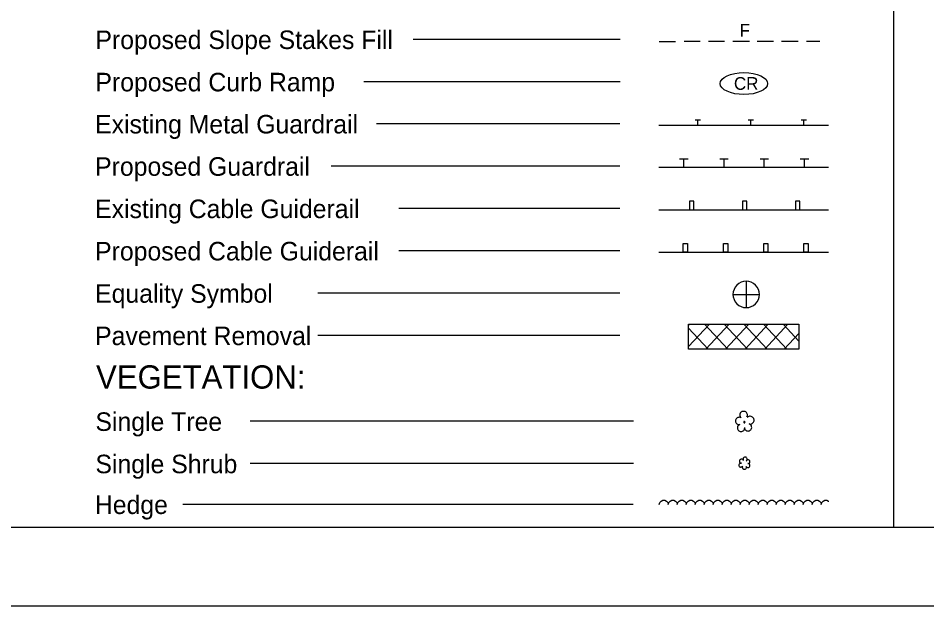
# Model space of a CAD drawing. Extents: x 1855058 to 1858918, y 1540202 to 1542502.
# Drawn here: x 1857551.6 to 1857984.5, y 1541401.8 to 1541681.9 of the extents above; entities that cross this region are included whole.
import ezdxf

# ---------------------------------------------------------------- set-up
doc = ezdxf.new("R2010")
doc.units = 0
for name, color, linetype in [('Default', 7, 'Continuous'), ('Exist Contamination Potential Cell', 7, 'Continuous'), ('Sheet Data Field CELL', 7, 'Continuous'), ('Sheet Symbology CELL', 7, 'Continuous'), ('z - Construction', 7, 'Continuous')]:
    doc.layers.add(name, color=color, linetype=linetype)

msp = doc.modelspace()

# ---------------------------------------------------------------- linework, layer by layer
at = {"layer": 'Default'}
msp.add_lwpolyline([(1857118.6, 1542501.77), (1857118.6, 1541401.77), (1858818.6, 1541401.77), (1858818.6, 1542501.77)], close=True, dxfattribs=at)
at = {"layer": 'Exist Contamination Potential Cell'}
for p, q in [((1857968.6, 1542464.27), (1857968.58, 1541439.27)), ((1857118.6, 1541401.77), (1858818.6, 1541401.77))]:
    msp.add_line(p, q, dxfattribs=at)
at = {"layer": 'Sheet Data Field CELL'}
for p, q in [((1857838.33, 1541671.75), (1857739.72, 1541671.75)), ((1857857.03, 1541670.69), (1857864.69, 1541670.69)), ((1857876.5, 1541670.69), (1857868.88, 1541670.69)), ((1857888.1, 1541670.69), (1857880.43, 1541670.69)), ((1857899.96, 1541670.69), (1857892.09, 1541670.69)), ((1857911.51, 1541670.69), (1857903.69, 1541670.69)), ((1857923.16, 1541670.69), (1857915.24, 1541670.69)), ((1857933.55, 1541670.69), (1857927.1, 1541670.69)), ((1857838.33, 1541651.57), (1857716.32, 1541651.57)), ((1857838.17, 1541631.51), (1857722.31, 1541631.51)), ((1857856.87, 1541630.93), (1857937.58, 1541630.93)), ((1857874.16, 1541633.45), (1857876.68, 1541633.45)), ((1857875.42, 1541630.93), (1857875.42, 1541633.45)), ((1857899.38, 1541633.45), (1857901.9, 1541633.45)), ((1857900.64, 1541630.93), (1857900.64, 1541633.45)), ((1857924.61, 1541633.45), (1857927.13, 1541633.45)), ((1857925.87, 1541630.93), (1857925.87, 1541633.45)), ((1857866.68, 1541614.74), (1857870.72, 1541614.74)), ((1857868.7, 1541610.75), (1857868.7, 1541614.74)), ((1857885.85, 1541614.74), (1857889.89, 1541614.74)), ((1857887.87, 1541610.75), (1857887.87, 1541614.74)), ((1857905.02, 1541614.74), (1857909.06, 1541614.74)), ((1857907.04, 1541610.75), (1857907.04, 1541614.74)), ((1857924.19, 1541614.74), (1857928.22, 1541614.74)), ((1857926.21, 1541610.75), (1857926.21, 1541614.74)), ((1857838.17, 1541611.33), (1857700.72, 1541611.33)), ((1857937.58, 1541610.75), (1857856.87, 1541610.75)), ((1857838.17, 1541591.15), (1857732.94, 1541591.15)), ((1857856.87, 1541590.57), (1857937.58, 1541590.57)), ((1857838.17, 1541570.97), (1857732.94, 1541570.97)), ((1857856.87, 1541570.39), (1857937.58, 1541570.39)), ((1857898.46, 1541556.51), (1857898.46, 1541550.2)), ((1857838.17, 1541550.79), (1857694.27, 1541550.79)), ((1857892.16, 1541550.2), (1857898.46, 1541550.2)), ((1857898.46, 1541550.2), (1857898.46, 1541543.89)), ((1857898.46, 1541550.2), (1857904.77, 1541550.2)), ((1857870.94, 1541535.95), (1857923.51, 1541535.95)), ((1857870.94, 1541524.15), (1857870.94, 1541535.95)), ((1857870.94, 1541535.34), (1857871.5, 1541535.95)), ((1857870.94, 1541525.31), (1857880.88, 1541535.95)), ((1857889.66, 1541524.15), (1857878.56, 1541535.95)), ((1857879.17, 1541524.15), (1857890.26, 1541535.95)), ((1857898.99, 1541524.15), (1857887.94, 1541535.95)), ((1857888.5, 1541524.15), (1857899.65, 1541535.95)), ((1857908.37, 1541524.15), (1857897.28, 1541535.95)), ((1857897.88, 1541524.15), (1857908.98, 1541535.95)), ((1857917.76, 1541524.15), (1857906.61, 1541535.95)), ((1857907.26, 1541524.15), (1857918.31, 1541535.95)), ((1857923.51, 1541527.93), (1857915.99, 1541535.95)), ((1857923.51, 1541535.95), (1857923.51, 1541524.15)), ((1857838.17, 1541530.61), (1857694.27, 1541530.61)), ((1857880.28, 1541524.15), (1857870.94, 1541534.13)), ((1857916.6, 1541524.15), (1857923.51, 1541531.51)), ((1857923.51, 1541524.15), (1857870.94, 1541524.15)), ((1857844.81, 1541489.71), (1857662.07, 1541489.71)), ((1857844.81, 1541469.53), (1857662.07, 1541469.53)), ((1857844.54, 1541450.1), (1857629.95, 1541450.1)), ((1857857.04, 1541450.1), (1857857.35, 1541451.06)), ((1857857.35, 1541451.06), (1857857.95, 1541451.71)), ((1857857.95, 1541451.71), (1857858.76, 1541452.17)), ((1857858.76, 1541452.17), (1857859.72, 1541452.17)), ((1857859.72, 1541452.17), (1857860.52, 1541451.66)), ((1857860.52, 1541451.66), (1857861.08, 1541451.01)), ((1857861.08, 1541451.01), (1857861.28, 1541450.15)), ((1857861.33, 1541450.1), (1857861.63, 1541451.06)), ((1857861.63, 1541451.06), (1857862.24, 1541451.71)), ((1857862.24, 1541451.71), (1857863.05, 1541452.17)), ((1857863.05, 1541452.17), (1857864.01, 1541452.17)), ((1857864.01, 1541452.17), (1857864.81, 1541451.66)), ((1857864.81, 1541451.66), (1857865.37, 1541451.01)), ((1857865.37, 1541451.01), (1857865.57, 1541450.15)), ((1857865.62, 1541450.1), (1857865.92, 1541451.06)), ((1857865.92, 1541451.06), (1857866.53, 1541451.71)), ((1857866.53, 1541451.71), (1857867.34, 1541452.17)), ((1857867.34, 1541452.17), (1857868.29, 1541452.17)), ((1857868.29, 1541452.17), (1857869.1, 1541451.66)), ((1857869.1, 1541451.66), (1857869.66, 1541451.01)), ((1857869.66, 1541451.01), (1857869.86, 1541450.15)), ((1857869.91, 1541450.1), (1857870.21, 1541451.06)), ((1857870.21, 1541451.06), (1857870.82, 1541451.71)), ((1857870.82, 1541451.71), (1857871.62, 1541452.17)), ((1857871.62, 1541452.17), (1857872.58, 1541452.17)), ((1857872.58, 1541452.17), (1857873.39, 1541451.66)), ((1857873.39, 1541451.66), (1857873.94, 1541451.01)), ((1857873.94, 1541451.01), (1857874.15, 1541450.15)), ((1857874.2, 1541450.1), (1857874.5, 1541451.06)), ((1857874.5, 1541451.06), (1857875.1, 1541451.71)), ((1857875.1, 1541451.71), (1857875.91, 1541452.17)), ((1857875.91, 1541452.17), (1857876.87, 1541452.17)), ((1857876.87, 1541452.17), (1857877.68, 1541451.66)), ((1857877.68, 1541451.66), (1857878.23, 1541451.01)), ((1857878.23, 1541451.01), (1857878.43, 1541450.15)), ((1857878.48, 1541450.1), (1857878.79, 1541451.06)), ((1857878.79, 1541451.06), (1857879.39, 1541451.71)), ((1857879.39, 1541451.71), (1857880.2, 1541452.17)), ((1857880.2, 1541452.17), (1857881.16, 1541452.17)), ((1857881.16, 1541452.17), (1857881.96, 1541451.66)), ((1857881.96, 1541451.66), (1857882.52, 1541451.01)), ((1857882.52, 1541451.01), (1857882.72, 1541450.15)), ((1857882.77, 1541450.1), (1857883.07, 1541451.06)), ((1857883.07, 1541451.06), (1857883.68, 1541451.71)), ((1857883.68, 1541451.71), (1857884.49, 1541452.17)), ((1857884.49, 1541452.17), (1857885.45, 1541452.17)), ((1857885.45, 1541452.17), (1857886.25, 1541451.66)), ((1857886.25, 1541451.66), (1857886.81, 1541451.01)), ((1857886.81, 1541451.01), (1857887.01, 1541450.15)), ((1857887.06, 1541450.1), (1857887.36, 1541451.06)), ((1857887.36, 1541451.06), (1857887.97, 1541451.71)), ((1857887.97, 1541451.71), (1857888.78, 1541452.17)), ((1857888.78, 1541452.17), (1857889.73, 1541452.17)), ((1857889.73, 1541452.17), (1857890.54, 1541451.66)), ((1857890.54, 1541451.66), (1857891.1, 1541451.01)), ((1857891.1, 1541451.01), (1857891.3, 1541450.15)), ((1857891.35, 1541450.1), (1857891.65, 1541451.06)), ((1857891.65, 1541451.06), (1857892.26, 1541451.71)), ((1857892.26, 1541451.71), (1857893.06, 1541452.17)), ((1857893.06, 1541452.17), (1857894.02, 1541452.17)), ((1857894.02, 1541452.17), (1857894.83, 1541451.66)), ((1857894.83, 1541451.66), (1857895.38, 1541451.01)), ((1857895.38, 1541451.01), (1857895.59, 1541450.15)), ((1857895.64, 1541450.1), (1857895.94, 1541451.06)), ((1857895.94, 1541451.06), (1857896.54, 1541451.71)), ((1857896.54, 1541451.71), (1857897.35, 1541452.17)), ((1857897.35, 1541452.17), (1857898.31, 1541452.17)), ((1857898.31, 1541452.17), (1857899.12, 1541451.66)), ((1857899.12, 1541451.66), (1857899.67, 1541451.01)), ((1857899.67, 1541451.01), (1857899.87, 1541450.15)), ((1857899.92, 1541450.1), (1857900.23, 1541451.06)), ((1857900.23, 1541451.06), (1857900.83, 1541451.71)), ((1857900.83, 1541451.71), (1857901.64, 1541452.17)), ((1857901.64, 1541452.17), (1857902.6, 1541452.17)), ((1857902.6, 1541452.17), (1857903.4, 1541451.66)), ((1857903.4, 1541451.66), (1857903.96, 1541451.01)), ((1857903.96, 1541451.01), (1857904.16, 1541450.15)), ((1857904.21, 1541450.1), (1857904.51, 1541451.06)), ((1857904.51, 1541451.06), (1857905.12, 1541451.71)), ((1857905.12, 1541451.71), (1857905.93, 1541452.17)), ((1857905.93, 1541452.17), (1857906.89, 1541452.17)), ((1857906.89, 1541452.17), (1857907.69, 1541451.66)), ((1857907.69, 1541451.66), (1857908.25, 1541451.01)), ((1857908.25, 1541451.01), (1857908.45, 1541450.15)), ((1857908.5, 1541450.1), (1857908.8, 1541451.06)), ((1857908.8, 1541451.06), (1857909.41, 1541451.71)), ((1857909.41, 1541451.71), (1857910.22, 1541452.17)), ((1857910.22, 1541452.17), (1857911.17, 1541452.17)), ((1857911.17, 1541452.17), (1857911.98, 1541451.66)), ((1857911.98, 1541451.66), (1857912.54, 1541451.01)), ((1857912.54, 1541451.01), (1857912.74, 1541450.15)), ((1857912.79, 1541450.1), (1857913.09, 1541451.06)), ((1857913.09, 1541451.06), (1857913.7, 1541451.71)), ((1857913.7, 1541451.71), (1857914.5, 1541452.17)), ((1857914.5, 1541452.17), (1857915.46, 1541452.17)), ((1857915.46, 1541452.17), (1857916.27, 1541451.66)), ((1857916.27, 1541451.66), (1857916.82, 1541451.01)), ((1857916.82, 1541451.01), (1857917.03, 1541450.15)), ((1857917.08, 1541450.1), (1857917.38, 1541451.06)), ((1857917.38, 1541451.06), (1857917.98, 1541451.71)), ((1857917.98, 1541451.71), (1857918.79, 1541452.17)), ((1857918.79, 1541452.17), (1857919.75, 1541452.17)), ((1857919.75, 1541452.17), (1857920.56, 1541451.66)), ((1857920.56, 1541451.66), (1857921.11, 1541451.01)), ((1857921.11, 1541451.01), (1857921.31, 1541450.15)), ((1857921.36, 1541450.1), (1857921.67, 1541451.06)), ((1857921.67, 1541451.06), (1857922.27, 1541451.71)), ((1857922.27, 1541451.71), (1857923.08, 1541452.17)), ((1857923.08, 1541452.17), (1857924.04, 1541452.17)), ((1857924.04, 1541452.17), (1857924.84, 1541451.66)), ((1857924.84, 1541451.66), (1857925.4, 1541451.01)), ((1857925.4, 1541451.01), (1857925.6, 1541450.15)), ((1857925.65, 1541450.1), (1857925.95, 1541451.06)), ((1857925.95, 1541451.06), (1857926.56, 1541451.71)), ((1857926.56, 1541451.71), (1857927.37, 1541452.17)), ((1857927.37, 1541452.17), (1857928.33, 1541452.17)), ((1857928.33, 1541452.17), (1857929.13, 1541451.66)), ((1857929.13, 1541451.66), (1857929.69, 1541451.01)), ((1857929.69, 1541451.01), (1857929.89, 1541450.15)), ((1857929.94, 1541450.1), (1857930.24, 1541451.06)), ((1857930.24, 1541451.06), (1857930.85, 1541451.71)), ((1857930.85, 1541451.71), (1857931.66, 1541452.17)), ((1857931.66, 1541452.17), (1857932.61, 1541452.17)), ((1857932.61, 1541452.17), (1857933.42, 1541451.66)), ((1857933.42, 1541451.66), (1857933.98, 1541451.01)), ((1857933.98, 1541451.01), (1857934.18, 1541450.15)), ((1857934.23, 1541450.1), (1857934.53, 1541451.06)), ((1857934.53, 1541451.06), (1857935.14, 1541451.71)), ((1857935.14, 1541451.71), (1857935.94, 1541452.17)), ((1857935.94, 1541452.17), (1857936.9, 1541452.17)), ((1857936.9, 1541452.17), (1857937.71, 1541451.66)), ((1857937.71, 1541451.66), (1857937.76, 1541451.61))]:
    msp.add_line(p, q, dxfattribs=at)
for points in [[(1857871.47, 1541590.57), (1857873.49, 1541590.57), (1857873.49, 1541594.61), (1857871.47, 1541594.61)], [(1857896.7, 1541590.57), (1857898.71, 1541590.57), (1857898.71, 1541594.61), (1857896.7, 1541594.61)], [(1857921.92, 1541590.57), (1857923.94, 1541590.57), (1857923.94, 1541594.61), (1857921.92, 1541594.61)], [(1857868.43, 1541574.43), (1857870.45, 1541574.43), (1857870.45, 1541570.39), (1857868.43, 1541570.39)], [(1857887.6, 1541574.43), (1857889.62, 1541574.43), (1857889.62, 1541570.39), (1857887.6, 1541570.39)], [(1857906.77, 1541574.43), (1857908.79, 1541574.43), (1857908.79, 1541570.39), (1857906.77, 1541570.39)], [(1857925.94, 1541574.43), (1857927.96, 1541574.43), (1857927.96, 1541570.39), (1857925.94, 1541570.39)]]:
    msp.add_lwpolyline(points, close=True, dxfattribs=at)
for points in [[(1857898.82, 1541491.81), (1857898.98, 1541492.17), (1857899.06, 1541492.53), (1857899.02, 1541492.93), (1857898.94, 1541493.28), (1857898.74, 1541493.64), (1857898.55, 1541493.92), (1857898.23, 1541494.2), (1857897.91, 1541494.36), (1857897.51, 1541494.47), (1857897.16, 1541494.47), (1857896.76, 1541494.44), (1857896.4, 1541494.32), (1857896.08, 1541494.12), (1857895.8, 1541493.84), (1857895.61, 1541493.52), (1857895.45, 1541493.16), (1857895.41, 1541492.81), (1857895.41, 1541492.41), (1857895.49, 1541492.05), (1857895.65, 1541491.7), (1857895.88, 1541491.38), (1857895.57, 1541491.54), (1857895.21, 1541491.62), (1857894.85, 1541491.58), (1857894.49, 1541491.5), (1857894.18, 1541491.34), (1857893.86, 1541491.1), (1857893.66, 1541490.82), (1857893.46, 1541490.5), (1857893.38, 1541490.19), (1857893.34, 1541489.79), (1857893.38, 1541489.43), (1857893.54, 1541489.11), (1857893.74, 1541488.79), (1857893.98, 1541488.56), (1857894.3, 1541488.36), (1857894.61, 1541488.2), (1857894.97, 1541488.16), (1857895.33, 1541488.16), (1857895.01, 1541488), (1857894.73, 1541487.76), (1857894.53, 1541487.48), (1857894.37, 1541487.13), (1857894.3, 1541486.77), (1857894.26, 1541486.41), (1857894.34, 1541486.05), (1857894.49, 1541485.74), (1857894.69, 1541485.42), (1857894.93, 1541485.18), (1857895.25, 1541484.98), (1857895.61, 1541484.86), (1857895.96, 1541484.82), (1857896.32, 1541484.86), (1857896.68, 1541484.94), (1857897, 1541485.14), (1857897.27, 1541485.38), (1857897.47, 1541485.66), (1857897.63, 1541485.97), (1857897.71, 1541486.33)], [(1857897.59, 1541486.77), (1857897.63, 1541486.37), (1857897.75, 1541486.02), (1857897.95, 1541485.7), (1857898.23, 1541485.42), (1857898.55, 1541485.22), (1857898.9, 1541485.1), (1857899.3, 1541485.06), (1857899.66, 1541485.1), (1857900.02, 1541485.22), (1857900.33, 1541485.42), (1857900.61, 1541485.66), (1857900.85, 1541485.97), (1857900.97, 1541486.33), (1857901.05, 1541486.69), (1857901.01, 1541487.09), (1857900.93, 1541487.44), (1857900.73, 1541487.8), (1857900.49, 1541488.08), (1857900.17, 1541488.28), (1857899.82, 1541488.44), (1857900.21, 1541488.4), (1857900.61, 1541488.4), (1857900.97, 1541488.52), (1857901.33, 1541488.68), (1857901.64, 1541488.91), (1857901.88, 1541489.23), (1857902.08, 1541489.59), (1857902.16, 1541489.95), (1857902.2, 1541490.34), (1857902.12, 1541490.74), (1857902, 1541491.1), (1857901.76, 1541491.42), (1857901.49, 1541491.7), (1857901.17, 1541491.89), (1857900.77, 1541492.05), (1857900.41, 1541492.09), (1857900.02, 1541492.09), (1857899.62, 1541491.97), (1857899.3, 1541491.77), (1857898.98, 1541491.54)], [(1857897.71, 1541489.59), (1857897.55, 1541489.59), (1857897.39, 1541489.55), (1857897.31, 1541489.43), (1857897.27, 1541489.27), (1857897.31, 1541489.11), (1857897.43, 1541488.99), (1857897.59, 1541488.99), (1857897.75, 1541489.03), (1857897.87, 1541489.15), (1857897.91, 1541489.31), (1857897.83, 1541489.47), (1857897.71, 1541489.59)], [(1857897.12, 1541471), (1857897, 1541471.24), (1857896.76, 1541471.44), (1857896.52, 1541471.6), (1857896.24, 1541471.64), (1857895.96, 1541471.6), (1857895.69, 1541471.52), (1857895.45, 1541471.32), (1857895.29, 1541471.08), (1857895.21, 1541470.8), (1857895.21, 1541470.52), (1857895.29, 1541470.25), (1857895.45, 1541470.01), (1857895.69, 1541469.81), (1857895.96, 1541469.69), (1857896.24, 1541469.69), (1857895.96, 1541469.73), (1857895.69, 1541469.73), (1857895.45, 1541469.65), (1857895.21, 1541469.49), (1857895.05, 1541469.29), (1857894.97, 1541469.05), (1857894.93, 1541468.77), (1857894.97, 1541468.5), (1857895.09, 1541468.26), (1857895.29, 1541468.06), (1857895.53, 1541467.94), (1857895.77, 1541467.86), (1857896.04, 1541467.9), (1857896.28, 1541467.98), (1857896.52, 1541468.14), (1857896.68, 1541468.34), (1857896.56, 1541468.06), (1857896.52, 1541467.78), (1857896.6, 1541467.5), (1857896.72, 1541467.27), (1857896.92, 1541467.03), (1857897.16, 1541466.91), (1857897.43, 1541466.83), (1857897.71, 1541466.87), (1857897.99, 1541466.95), (1857898.23, 1541467.11), (1857898.39, 1541467.34), (1857898.51, 1541467.62), (1857898.51, 1541467.9), (1857898.47, 1541468.18), (1857898.59, 1541467.98), (1857898.82, 1541467.78), (1857899.06, 1541467.7), (1857899.34, 1541467.66), (1857899.62, 1541467.7), (1857899.86, 1541467.82), (1857900.06, 1541468.02), (1857900.17, 1541468.26), (1857900.21, 1541468.54), (1857900.21, 1541468.81), (1857900.1, 1541469.05), (1857899.94, 1541469.25), (1857899.74, 1541469.41), (1857899.46, 1541469.53), (1857899.18, 1541469.53), (1857899.46, 1541469.53), (1857899.74, 1541469.61), (1857899.94, 1541469.77), (1857900.14, 1541470.01), (1857900.21, 1541470.25), (1857900.21, 1541470.52), (1857900.17, 1541470.8), (1857900.02, 1541471.04), (1857899.82, 1541471.2), (1857899.54, 1541471.32), (1857899.26, 1541471.36), (1857899.02, 1541471.28), (1857898.74, 1541471.16), (1857898.59, 1541470.96), (1857898.47, 1541470.72)], [(1857898.35, 1541470.72), (1857898.59, 1541470.84), (1857898.78, 1541471.08), (1857898.9, 1541471.32), (1857898.94, 1541471.6), (1857898.94, 1541471.87), (1857898.82, 1541472.15), (1857898.66, 1541472.35), (1857898.47, 1541472.55), (1857898.19, 1541472.63), (1857897.91, 1541472.67), (1857897.63, 1541472.63), (1857897.39, 1541472.51), (1857897.16, 1541472.31), (1857897.04, 1541472.07), (1857896.96, 1541471.79), (1857896.96, 1541471.52), (1857897, 1541471.24), (1857897.16, 1541471)]]:
    msp.add_lwpolyline(points, dxfattribs=at)
for start, end in [(89.9944, 179.9989), (359.9944, 89.9989), (179.9944, 269.9989), (269.9944, 359.9989)]:
    msp.add_arc((1857898.46, 1541550.2), 6.31, start, end, dxfattribs=at)
at = {"layer": 'Sheet Symbology CELL'}
msp.add_line((1857156.1, 1541439.27), (1858781.08, 1541439.27), dxfattribs=at)
at = {"layer": 'z - Construction'}
msp.add_ellipse((1857897.35, 1541650.69), major_axis=(11.31, 0), ratio=0.462467, dxfattribs=at)

# ---------------------------------------------------------------- texts
at = {"layer": 'Sheet Data Field CELL'}
for s, height, p in [('F', 5.98, (1857895.37, 1541673.07)), ('Proposed Slope Stakes Fill', 8.8282, (1857588.37, 1541667.15)), ('Proposed Curb Ramp', 8.8282, (1857588.37, 1541646.98)), ('Existing Metal Guardrail', 8.8282, (1857588.21, 1541626.92)), ('Proposed Guardrail', 8.8282, (1857588.22, 1541606.75)), ('Existing Cable Guiderail', 8.8282, (1857588.22, 1541586.57)), ('Proposed Cable Guiderail', 8.8282, (1857588.22, 1541566.39)), ('Equality Symbol', 8.8282, (1857588.22, 1541546.22)), ('Pavement Removal', 8.8282, (1857588.22, 1541526.04)), ('VEGETATION:', 11.0983, (1857588.65, 1541505.3)), ('Single Tree', 8.8282, (1857588.38, 1541485.14)), ('Single Shrub', 8.8282, (1857588.38, 1541464.96)), ('Hedge', 8.828, (1857588.11, 1541445.53))]:
    msp.add_text(s, height=height, dxfattribs=at).set_placement(p)
at = {"layer": 'z - Construction'}
msp.add_text('CR', height=6.054, dxfattribs=at).set_placement((1857892.59, 1541647.71))

doc.saveas('drawing.dxf')
